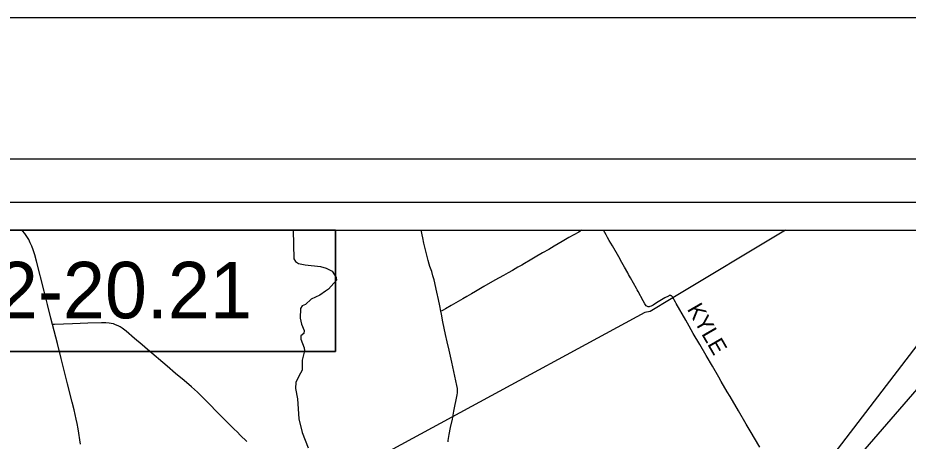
# Model space of a CAD drawing. Extents: x -19.5 to 44.1, y 0 to 22.
# Drawn here: x 3.546 to 6.7, y 20.5 to 22 of the extents above; entities that cross this region are included whole.
import ezdxf

# ---------------------------------------------------------------- set-up
doc = ezdxf.new("R2010")
doc.units = 0
for name, color, linetype in [('GM_X_County_Road', 7, 'Continuous'), ('GM_X_Minor_River', 7, 'Continuous'), ('GM_X_State_Route', 7, 'Continuous'), ('GM_X_Township', 7, 'Continuous'), ('GM_X_Township_Road', 7, 'Continuous'), ('GM_X_Township_Road_Text', 7, 'Continuous'), ('SH_Border', 7, 'Continuous'), ('SH_Cut_Line', 7, 'Continuous'), ('SH_Data', 7, 'Continuous'), ('SH_Masking', 7, 'Continuous'), ('SH_Text', 7, 'Continuous')]:
    doc.layers.add(name, color=color, linetype=linetype)

msp = doc.modelspace()

# ---------------------------------------------------------------- linework, layer by layer
at = {"layer": 'GM_X_County_Road'}
for points in [[(5.0442, 20.9605), (5.0409, 20.9791), (5.0363, 21.0023), (5.0306, 21.0284), (5.0205, 21.0714), (5.0166, 21.0864), (5.012, 21.1013), (5.006, 21.1187), (5.0027, 21.1278), (4.9994, 21.1402), (4.9932, 21.1642), (4.9847, 21.2017), (4.9803, 21.2205), (4.9743, 21.2473)], [(5.0852, 20.5786), (5.0908, 20.6059), (5.1027, 20.6644), (5.1038, 20.6719), (5.1039, 20.6788), (5.1032, 20.6863), (5.1012, 20.6974), (5.0832, 20.7799), (5.0736, 20.8224), (5.0671, 20.8521), (5.0615, 20.8782), (5.0516, 20.9224), (5.0462, 20.9498), (5.0442, 20.9605)], [(4.3565, 20.4994), (4.3339, 20.5212), (4.3236, 20.5315), (4.3115, 20.5438), (4.3034, 20.5515), (4.2775, 20.5774), (4.2554, 20.5998), (4.2203, 20.6359), (4.194, 20.6623), (4.1823, 20.6734), (4.161, 20.6924), (4.1352, 20.7148), (4.1048, 20.7404), (4.0744, 20.766), (4.0052, 20.8247), (3.9863, 20.8409), (3.9594, 20.8639), (3.9289, 20.8894), (3.9153, 20.9002), (3.9082, 20.905), (3.9012, 20.9089), (3.8922, 20.9128), (3.8846, 20.9153), (3.8768, 20.9171), (3.8695, 20.9181), (3.8572, 20.9189), (3.8423, 20.9189), (3.7939, 20.9179), (3.7399, 20.916), (3.6753, 20.9139), (3.6685, 20.9137)], [(5.0701, 20.498), (5.0705, 20.503), (5.0712, 20.5091), (5.0738, 20.5232), (5.079, 20.5481), (5.0852, 20.5786)]]:
    msp.add_lwpolyline(points, dxfattribs=at)
at = {"layer": 'GM_X_Minor_River'}
msp.add_lwpolyline([(4.5211, 21.2473), (4.5231, 21.1462), (4.5294, 21.1362), (4.5399, 21.1295), (4.5633, 21.1248), (4.6175, 21.1188), (4.6386, 21.1131), (4.6589, 21.1024), (4.6737, 21.0804), (4.675, 21.0705), (4.6463, 21.0381), (4.6356, 21.0311), (4.616, 21.017), (4.5846, 21.0036), (4.5645, 20.9843), (4.5531, 20.9796), (4.5472, 20.9698), (4.5462, 20.936), (4.5508, 20.9147), (4.5598, 20.8921), (4.5585, 20.8811), (4.5481, 20.8733), (4.5479, 20.8619), (4.5606, 20.8313), (4.5612, 20.8203), (4.553, 20.7874), (4.5527, 20.7521), (4.5476, 20.7408), (4.5303, 20.7089), (4.5295, 20.6869), (4.5368, 20.6502), (4.5416, 20.5788), (4.5525, 20.5314), (4.5738, 20.4763)], dxfattribs=at)
at = {"layer": 'GM_X_State_Route'}
msp.add_lwpolyline([(3.7672, 20.4891), (3.7589, 20.5438), (3.7559, 20.5628), (3.7528, 20.5786), (3.7455, 20.6107), (3.7387, 20.6384), (3.722, 20.7034), (3.6995, 20.7932), (3.6857, 20.8461), (3.6685, 20.9137), (3.6628, 20.9358), (3.6508, 20.9841), (3.6391, 21.0317), (3.6121, 21.1377), (3.6058, 21.1597), (3.6002, 21.1775), (3.5953, 21.1908), (3.5897, 21.2033), (3.5841, 21.2143), (3.5777, 21.2249), (3.5703, 21.2356), (3.5627, 21.2453), (3.5609, 21.2473)], dxfattribs=at)
at = {"layer": 'GM_X_Township'}
msp.add_lwpolyline([(6.2655, 21.2473), (5.8607, 21.0044), (5.7861, 20.9597), (5.7667, 20.9559), (5.083, 20.5848), (4.8327, 20.449), (4.8314, 20.1547), (4.831, 20.0704), (4.7315, 20.0669), (3.9932, 20.0408), (3.8179, 20.0322), (3.8137, 20.032), (3.8924, 19.5403), (3.1773, 19.5948), (2.6599, 19.6343), (2.6, 19.6388)], dxfattribs=at)
at = {"layer": 'GM_X_Township_Road'}
for points in [[(5.5432, 21.2473), (5.533, 21.2411), (5.4978, 21.2215), (5.4742, 21.2077), (5.4456, 21.1905), (5.4268, 21.1796), (5.4046, 21.167), (5.3782, 21.1519), (5.3607, 21.1414), (5.341, 21.1294), (5.3308, 21.1235), (5.3178, 21.1164), (5.298, 21.105), (5.2834, 21.0967), (5.266, 21.0874), (5.2511, 21.0786), (5.2358, 21.0701), (5.1972, 21.0478), (5.1677, 21.0308), (5.1528, 21.022), (5.137, 21.0129), (5.1228, 21.0047), (5.0889, 20.9852), (5.0805, 20.9803), (5.0611, 20.9691), (5.0525, 20.9645), (5.0477, 20.9622), (5.0442, 20.9605)], [(5.7828, 20.9763), (5.7818, 20.9759), (5.7785, 20.976), (5.7762, 20.9768), (5.7739, 20.9782), (5.7721, 20.98), (5.7699, 20.9826), (5.7672, 20.9869), (5.7611, 20.9978), (5.7436, 21.03), (5.7399, 21.0365), (5.7372, 21.0413), (5.7271, 21.0599), (5.7165, 21.0789), (5.7099, 21.0908), (5.7064, 21.0966), (5.6955, 21.1161), (5.6859, 21.1335), (5.6749, 21.1529), (5.6522, 21.1922), (5.641, 21.2114), (5.6352, 21.2215), (5.6297, 21.2317), (5.6213, 21.2473)], [(5.8605, 21.0156), (5.8598, 21.0159), (5.859, 21.0162), (5.8568, 21.0165), (5.854, 21.0159), (5.8508, 21.0144), (5.8384, 21.0074), (5.8149, 20.9935), (5.8047, 20.9877), (5.7962, 20.9825), (5.7896, 20.9789), (5.7852, 20.977), (5.7828, 20.9763)], [(6.1744, 20.4793), (6.1561, 20.5104), (6.1442, 20.5307), (6.1264, 20.5606), (6.0988, 20.6079), (6.0692, 20.6589), (6.0594, 20.6755), (6.0381, 20.712), (6.0292, 20.7269), (6.0067, 20.7656), (5.9848, 20.8038), (5.9623, 20.8425), (5.9388, 20.8821), (5.9238, 20.9078), (5.9119, 20.9289), (5.8783, 20.9877), (5.8758, 20.9921), (5.8653, 21.0115), (5.8634, 21.0137), (5.8611, 21.0154), (5.8605, 21.0156)]]:
    msp.add_lwpolyline(points, dxfattribs=at)
at = {"layer": 'SH_Border'}
msp.add_lwpolyline([(2, 21.5), (33.5, 21.5), (33.5, 0.5), (2, 0.5)], close=True, dxfattribs=at)
at = {"layer": 'SH_Cut_Line'}
msp.add_lwpolyline([(0, 0), (34, 0), (34, 22), (0, 22)], close=True, dxfattribs=at)
at = {"layer": 'SH_Data'}
for p, q in [((2.5, 21.3473), (9.5, 21.3473)), ((2.6, 21.2473), (9.4, 21.2473))]:
    msp.add_line(p, q, dxfattribs=at)
at = {"layer": 'SH_Masking'}
msp.add_lwpolyline([(2.6, 21.2473), (4.6707, 21.2473), (4.6707, 20.8184), (2.6, 20.8184)], close=True, dxfattribs=at)
at = {"layer": 'SH_Text'}
for points in [[(2.6, 20.8184), (4.6707, 20.8184), (4.6707, 21.2473), (2.6, 21.2473)], [(7.0453, 21.0473), (5.7192, 19.517), (7.0453, 21.2473)]]:
    msp.add_lwpolyline(points, close=True, dxfattribs=at)

# ---------------------------------------------------------------- texts
at = {"layer": 'GM_X_Township_Road_Text'}
msp.add_text('KYLE', height=0.05682, rotation=300.0553, dxfattribs=at).set_placement((5.9154, 20.9683))
at = {"layer": 'SH_Text'}
msp.add_text('GRE-42-20.21', height=0.2, rotation=360, dxfattribs=at).set_placement((2.6504, 20.9354))

doc.saveas('drawing.dxf')
